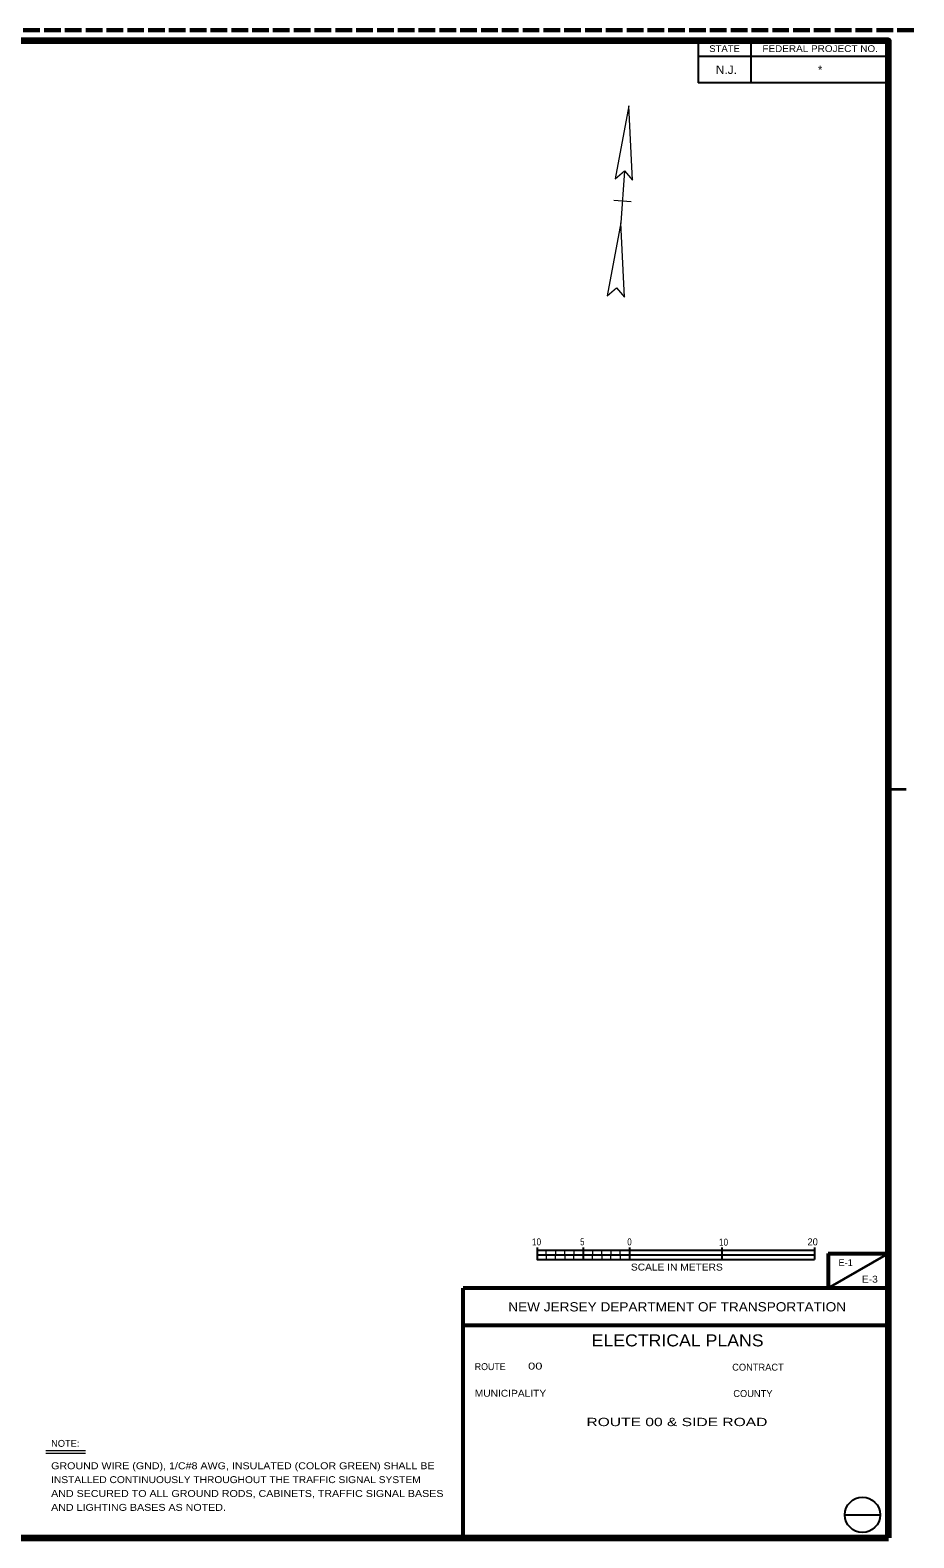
# Model space of a CAD drawing. Extents: x 168203 to 169864, y 223196 to 223870.
# Drawn here: x 169268.5 to 169364, y 223536.2 to 223699.4 of the extents above; entities that cross this region are included whole.
import ezdxf
from ezdxf.enums import TextEntityAlignment as Align

# ---------------------------------------------------------------- set-up
doc = ezdxf.new("R2010")
doc.units = 0
doc.header["$LTSCALE"] = 0.3
doc.linetypes.add('LONG_DASHED', pattern=[7.5, 6, -1.5])
for name, color, linetype, lineweight in [('1', 7, 'Continuous', 13), ('10', 7, 'Continuous', 13), ('25', 7, 'Continuous', 35)]:
    doc.layers.add(name, color=color, linetype=linetype, lineweight=lineweight)

msp = doc.modelspace()

# ---------------------------------------------------------------- linework, layer by layer
at = {"layer": '1', "linetype": 'LONG_DASHED', "lineweight": 60}
msp.add_line((169364.0333, 223699.3889), (169095.8093, 223699.3889), dxfattribs=at)
at = {"layer": '1', "lineweight": 25}
for p, q in [((169340.7093, 223698.2489), (169340.7093, 223693.6769)), ((169346.4243, 223698.2489), (169346.4243, 223693.6769)), ((169361.2833, 223696.5344), (169340.7093, 223696.5344)), ((169361.2833, 223693.6769), (169340.7093, 223693.6769)), ((169323.2833, 223567.3626), (169353.2833, 223567.3626)), ((169325.1233, 223567.3626), (169326.1433, 223567.3626)), ((169327.1633, 223567.3626), (169328.1833, 223567.3626)), ((169328.2833, 223567.6601), (169328.2833, 223566.3626)), ((169329.2033, 223567.3626), (169330.2233, 223567.3626)), ((169331.2433, 223567.3626), (169332.2633, 223567.3626)), ((169333.2833, 223567.6601), (169333.2833, 223566.3626)), ((169343.2833, 223567.6601), (169343.2833, 223566.3626)), ((169353.2833, 223567.6601), (169353.2833, 223566.3626)), ((169323.2833, 223566.8626), (169353.2833, 223566.8626))]:
    msp.add_line(p, q, dxfattribs=at)
at = {"layer": '1'}
for p, q in [((169332.7433, 223684.1727), (169332.3558, 223678.5385)), ((169332.5176, 223680.8913), (169331.58, 223680.9558)), ((169333.4552, 223680.8268), (169332.5176, 223680.8913))]:
    msp.add_line(p, q, dxfattribs=at)
at = {"layer": '1', "lineweight": 35}
msp.add_line((169361.2833, 223617.2489), (169363.2033, 223617.2489), dxfattribs=at)
at = {"layer": '1', "lineweight": 158}
msp.add_lwpolyline([(169361.2833, 223536.2489), (169361.2833, 223698.2489), (169128.7833, 223698.2489), (169128.7833, 223536.2489)], close=True, dxfattribs=at)
at = {"layer": '1'}
for points in [[(169331.7412, 223683.2997), (169332.7433, 223684.1727), (169333.6164, 223683.1707), (169333.2276, 223691.2133)], [(169330.8694, 223670.6248), (169331.8715, 223671.4978), (169332.7446, 223670.4958), (169332.3558, 223678.5385)], [(169323.2833, 223566.8626), (169324.2833, 223566.8626), (169324.2833, 223567.3626), (169323.2833, 223567.3626)], [(169325.2833, 223566.8626), (169326.2833, 223566.8626), (169326.2833, 223567.3626), (169325.2833, 223567.3626)], [(169327.2833, 223566.8626), (169328.2833, 223566.8626), (169328.2833, 223567.3626), (169327.2833, 223567.3626)], [(169329.2833, 223566.8626), (169330.2833, 223566.8626), (169330.2833, 223567.3626), (169329.2833, 223567.3626)], [(169331.2833, 223566.8626), (169332.2833, 223566.8626), (169332.2833, 223567.3626), (169331.2833, 223567.3626)], [(169333.2833, 223566.8626), (169343.2833, 223566.8626), (169343.2833, 223567.3626), (169333.2833, 223567.3626)], [(169324.2833, 223566.3626), (169325.2833, 223566.3626), (169325.2833, 223566.8626), (169324.2833, 223566.8626)], [(169326.2833, 223566.3626), (169327.2833, 223566.3626), (169327.2833, 223566.8626), (169326.2833, 223566.8626)], [(169328.2833, 223566.3626), (169329.2833, 223566.3626), (169329.2833, 223566.8626), (169328.2833, 223566.8626)], [(169330.2833, 223566.3626), (169331.2833, 223566.3626), (169331.2833, 223566.8626), (169330.2833, 223566.8626)], [(169332.2833, 223566.3626), (169333.2833, 223566.3626), (169333.2833, 223566.8626), (169332.2833, 223566.8626)], [(169343.2833, 223566.3626), (169353.2833, 223566.3626), (169353.2833, 223566.8626), (169343.2833, 223566.8626)]]:
    msp.add_lwpolyline(points, close=True, dxfattribs=at)
at = {"layer": '1', "lineweight": 25}
msp.add_lwpolyline([(169323.2833, 223567.6601), (169323.2833, 223566.3626), (169353.2833, 223566.3626)], dxfattribs=at)
at = {"layer": '10'}
for p, q in [((169270.1818, 223545.6831), (169274.4608, 223545.6831)), ((169270.1818, 223545.4086), (169274.4608, 223545.4086))]:
    msp.add_line(p, q, dxfattribs=at)
at = {"layer": '25'}
msp.add_line((169354.7833, 223563.2489), (169361.2833, 223566.9989), dxfattribs=at)
at = {"layer": '25', "lineweight": 53}
for p, q in [((169354.7833, 223566.9989), (169361.2833, 223566.9989)), ((169354.7833, 223566.9989), (169354.7833, 223563.2489)), ((169315.2833, 223536.2489), (169315.2833, 223563.2489)), ((169361.2833, 223563.2489), (169315.2833, 223563.2489)), ((169315.2833, 223559.2489), (169361.2833, 223559.2489))]:
    msp.add_line(p, q, dxfattribs=at)
at = {"layer": '25', "lineweight": 25}
msp.add_line((169356.5733, 223538.7389), (169360.3833, 223538.7389), dxfattribs=at)
msp.add_circle((169358.4782, 223538.7389), 1.9049, dxfattribs=at)

# ---------------------------------------------------------------- texts
at = {"layer": '1'}
for s, height, width, p in [('STATE', 0.7315, 1.05, (169343.5668, 223697.0259)), ('FEDERAL PROJECT NO.', 0.7315, 1.1, (169353.9028, 223697.0259)), ('N.J.', 0.9144, 1.05, (169343.7648, 223694.6484)), ('10', 0.7501, 0.9, (169323.2342, 223567.9026)), ('5', 0.7501, 0.75, (169328.1859, 223567.9026)), ('0', 0.7501, 0.85, (169333.2884, 223567.9026)), ('10', 0.7501, 0.9, (169343.4542, 223567.8726)), ('SCALE IN METERS', 0.7501, 1.1, (169338.4047, 223565.1726))]:
    msp.add_text(s, height=height, dxfattribs=dict(at, width=width)).set_placement(p, align=Align.CENTER)
for s, height, p in [('*', 0.9144, (169353.9028, 223694.6399)), ('20', 0.7501, (169353.095, 223567.9026))]:
    msp.add_text(s, height=height, dxfattribs=at).set_placement(p, align=Align.CENTER)
at = {"layer": '10'}
msp.add_text('E-1', height=0.75, dxfattribs=at).set_placement((169356.6606, 223565.6529), align=Align.CENTER)
at = {"layer": '10', "width": 1.1}
for s, height, p in [('E-3', 0.75, (169359.2798, 223563.8635)), ('ELECTRICAL PLANS', 1.3, (169338.488, 223556.9656))]:
    msp.add_text(s, height=height, dxfattribs=at).set_placement(p, align=Align.CENTER)
at = {"layer": '10'}
msp.add_text('NOTE:', height=0.75, dxfattribs=at).set_placement((169270.7377, 223546.0976))
for s, width, p in [('GROUND WIRE (GND), 1/C#8 AWG, INSULATED (COLOR GREEN) SHALL BE', 1.15, (169270.7409, 223543.6718)), ('INSTALLED CONTINUOUSLY THROUGHOUT THE TRAFFIC SIGNAL SYSTEM', 1.1, (169270.7409, 223542.1718)), ('AND SECURED TO ALL GROUND RODS, CABINETS, TRAFFIC SIGNAL BASES', 1.15, (169270.7409, 223540.6718)), ('AND LIGHTING BASES AS NOTED.', 1.15, (169270.7409, 223539.1718))]:
    msp.add_text(s, height=0.75, dxfattribs=dict(at, width=width)).set_placement(p)
at = {"layer": '25'}
for s, height, width, p in [('NEW JERSEY DEPARTMENT OF TRANSPORTATION', 1, 1.1, (169338.4408, 223560.7489)), ('             ROUTE 00 & SIDE ROAD            ', 0.9, 1.4, (169338.181, 223548.3389))]:
    msp.add_text(s, height=height, dxfattribs=dict(at, width=width)).set_placement(p, align=Align.CENTER)
for s, width, p in [('ROUTE', 0.95, (169316.5533, 223554.3989)), ('00                        ', 1.4, (169322.3133, 223554.4589)), ('MUNICIPALITY', 1.1, (169316.5533, 223551.5189))]:
    msp.add_text(s, height=0.75, dxfattribs=dict(at, width=width)).set_placement(p)
for s, p in [('CONTRACT', (169344.3933, 223554.3389)), ('COUNTY', (169344.5133, 223551.4889))]:
    msp.add_text(s, height=0.75, dxfattribs=at).set_placement(p)

doc.saveas('drawing.dxf')
